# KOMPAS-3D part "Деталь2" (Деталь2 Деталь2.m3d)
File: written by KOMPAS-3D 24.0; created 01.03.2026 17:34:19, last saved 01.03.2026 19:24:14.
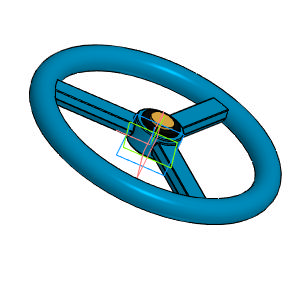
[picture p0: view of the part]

Document properties: Автор: R2D2; Полное имя файла: E:\Работа\Зайцев\GVWR3131M-2W-F-S Задвижка клиновая с выдвижным штоком DN.ru Ду50-200 Ру63\DN50\исходные материалы\Деталь2 Деталь2.m3d

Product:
- Body: Твердое тело1  | qty 1
    Масса: 3.95529
- Part/product: Деталь2
    Масса: 3.95529
    additional columns: Типовые

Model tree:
1. Твердое тело1  (labels: Твердое тело1)
2. Эскиз:1
3. Элемент выдавливания:1
     Расстояние 1 = 100
4. Эскиз:2
5. Элемент вращения:1
     Угол 1 = 360
6. Элемент выдавливания:2  (with: Грань.Элемент выдавливания:1)
     Расстояние 2 = 40
7. Массив по концентрической сетке:1  (with: Элемент выдавливания:2)  (labels: Грань.Твердое тело1)  (3 pattern instances)
     Шаг 2 = 360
